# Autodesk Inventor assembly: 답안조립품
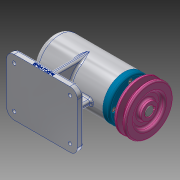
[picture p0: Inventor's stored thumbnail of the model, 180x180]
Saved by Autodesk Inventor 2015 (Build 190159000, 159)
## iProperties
Created: 2020-10
Part Number: 답안조립품
Document SubType Name: Assembly
Designer: Line503_02
Author: Line503_02
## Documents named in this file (12)
- C:\Users\Line503_02\Desktop\701004V1010\답안조립품.iam
- C:\Users\Line503_02\Desktop\701004V1010\본체.ipt
- C:\Users\Line503_02\Desktop\701004V1010\커버.ipt
- C:\Users\Line503_02\Desktop\701004V1010\베어링 6004.ipt
- C:\Users\Line503_02\Desktop\701004V1010\축.ipt
- C:\Users\Line503_02\Desktop\701004V1010\어댑터슬리브.ipt
- C:\Users\Line503_02\Desktop\701004V1010\볼트 M4.ipt
- C:\Users\Line503_02\Desktop\701004V1010\베어링 51202.ipt
- C:\Users\Line503_02\Desktop\701004V1010\키 5 x 5 x 16.ipt
- C:\Users\Line503_02\Desktop\701004V1010\오일 실.ipt
- C:\Users\Line503_02\Desktop\701004V1010\V벨트풀리.ipt
- C:\Users\Line503_02\Desktop\701004V1010\멈춤나사 M3.ipt
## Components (1 placed, 1 different names)
1. V벨트풀리:1 — 각도:4
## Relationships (1: Angle 1)
- 각도:4 [Angle]: V벨트풀리:1
